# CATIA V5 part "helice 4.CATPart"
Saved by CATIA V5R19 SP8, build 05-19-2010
Part number: helice 4
Bounding box of the stored display mesh (mm): x -17.321 to 17.321, y -30 to 195, z -10 to 20
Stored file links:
  G:\EU_thinkMotion\CFAO_2010\MMS_groupe2\MMS_groupe2\A reprendre\splanchenault\Planchenault\helice 4.CATPart
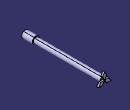
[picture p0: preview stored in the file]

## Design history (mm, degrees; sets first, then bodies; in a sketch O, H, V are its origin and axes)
Body1 (main body)
  Sketch1 on yz-plane, origin (0, 0, 0), H (0, 1, 0), V (0, 0, 1)
    line L1 (0, 0) -> (-30, 0)
    line L2 (-30, 0) -> (-30, 10)
    line L3 (0, 10) -> (-30, 10)
    line L4 (0, 10) -> (0, 7.5)
    line L5 (0, 7.5) -> (190, 7.5)
    line L6 (190, 7.5) -> (190, 0)
    line L7 (190, 0) -> (0, 0)
    length L6 = 7.5
    length L2 = 10
    length L3 = 30
    distance V L4 = 0
    length L5 = 190
    horizontal: L1 H, L3 H, L5 H, L7 H
    vertical: L2 V, L4 V, L6 V
  Shaft1: profile Sketch1, axis Sketch1.L7, angle 360
  Sketch2 on face of Shaft1 from Sketch1.L6, origin (0, 190, 0), H (-1, 0, 0), V (0, 0, 1)
    construction line L1 (27.3861, 15.8114) -> (-27.3861, -15.8114)
    axis line L2 (19.3649, -11.1803) -> (-19.3649, 11.1803)
    line L3 (0, 0) -> (5.7735, 10)
    point P5 (5.7735, 10)
    line L4 (0, 0) -> (-5.7735, 10)
    point P6 (-5.7735, 10)
    line L5 (-5.7735, 10) -> (0, 20)
    point P7 (0, 20)
    line L6 (0, 20) -> (5.7735, 10)
    point P8 (11.547, 0)
    point P9 (17.3205, -10)
    line L7 (17.3205, -10) -> (11.547, 0)
    point P10 (5.7735, -10)
    line L8 (5.7735, -10) -> (17.3205, -10)
    point P11 (0, 0)
    line L9 (0, 0) -> (5.7735, -10)
    line L10 (0, 0) -> (11.547, 0)
    point P12 (-11.547, 0)
    point P13 (0, 0)
    line L11 (0, 0) -> (-11.547, 0)
    point P14 (-5.7735, -10)
    line L12 (0, 0) -> (-5.7735, -10)
    point P15 (-17.3205, -10)
    line L13 (-17.3205, -10) -> (-5.7735, -10)
    line L14 (-11.547, 0) -> (-17.3205, -10)
    coincidence: L1 O, L2 O, P7 V, O P11, O P13, P11 P13
    perpendicularity: L3 L2, L4 L1
    parallelism: L5 L3
    symmetry: P5 P8 L1, P7 P9 L1, L6 L7 L1, P6 P10 L1, L5 L8 L1, O P11 L1, L4 L9 L1, L3 L10 L1, P6 P12 L2, O P13 L2, L4 L11 L2, P5 P14 L2, L3 L12 L2, P7 P15 L2, L6 L13 L2, L5 L14 L2
  Pad1: profile Sketch2, direction (0, 1, 0), length 5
